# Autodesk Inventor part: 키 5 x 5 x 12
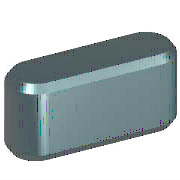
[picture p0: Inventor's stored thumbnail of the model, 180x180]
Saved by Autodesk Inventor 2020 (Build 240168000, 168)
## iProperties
Created: 2012-02
Part Number: 키 5 x 5 x 12
Material: 강철, 연강
Description: 키 및 해당 키홈
Document SubType Name: Modeling
Standard: KS B 1311
Designer: mduedu
Standards Organization: KS
Language: ko-KR
Size Designation: 5 x 5 x 12
Categories: <MemberInstance><Categories><Category DisplayName="샤프트 부품" InternalName="7f7aeb1f-a693-4053-b835-cee3144e0d98" Mnemonic="SHFT"><Category DisplayName="키" Interna
Density: 7.86 g/cm^3
Mass: 2.11085 g
Surface Area: 2.43471 cm^2
Volume: 0.268556 cm^3
Appearance: 노란색
IsCustomPart: 1
Author: mduedu
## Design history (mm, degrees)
workplane "Work Plane1"
workplane "Work Plane2"
sketch "스케치1"
  geometry: L1 (2.5, 2.5)-(9.5, 2.5); L2 (9.5, -2.5)-(2.5, -2.5); L3 (0, 9.4)-(0, -7.4) reference; L4 (-5, 0)-(30, 0) reference; L5 (12, 0)-(12, 7); A1 r 2.5 centre (2.5, 0) between (2.5, 2.5) and (2.5, -2.5); A2 r 2.5 centre (9.5, 0) between (9.5, -2.5) and (9.5, 2.5)
  constraints: 6 end point, 5 point on circle, 4 tangent, 3 point on line, 2 centre point, 1 horizontal, 1 parallel, 1 perpendicular
  dimensions: "d0" = 2.5 radius of A1 (= 0.5 x PB); "d13" = 2.5 radius of A2 (= 0.5 x PB); "d14" = 12 distance between parallel lines of L5 L3 (= NLG)
extrude "본체1" new body sketch "스케치1" taper "d3" = 0 deg; stored distance "d4" = 10
workplane "Work Plane3"
body "Solid1"
chamfer "모따기1" distance "d8" = 0.4 (= PHH); stored, may be unused: second distance "d9" = 0.4 (= PHH), angle "d15" = 45 deg
other parameters: "d1" = -3 (= -PNT), "d2" = 2 (= PH - PNT), "NLG" = 12 [user parameter; used in 3 equation terms], "PB" = 5 [user parameter; used in 2 equation terms], "PNT" = 3 [user parameter; used in 2 equation terms], "PH" = 5 [user parameter; used in 1 equation term], "PHH" = 0.4 [user parameter; used in 2 equation terms], "d10" = 0, "d16" = 0, "d17" = 0, "d18" = 0, "WDMIN" = 12 [user parameter], "PLB2" = 12 (= NLG) [user parameter], "WDMAX" = 17 [user parameter], "PLB1" = 12 (= NLG) [user parameter], "RR" = 0.16 [user parameter], "PUEB" = 2.3 [user parameter]
